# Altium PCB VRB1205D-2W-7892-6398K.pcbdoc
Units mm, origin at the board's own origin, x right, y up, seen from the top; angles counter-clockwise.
Board outline 59.6 x 39.6 mm, 2 copper layers (Top Layer, Bottom Layer); 30 components, 15 nets, 76 pads, 15 vias.
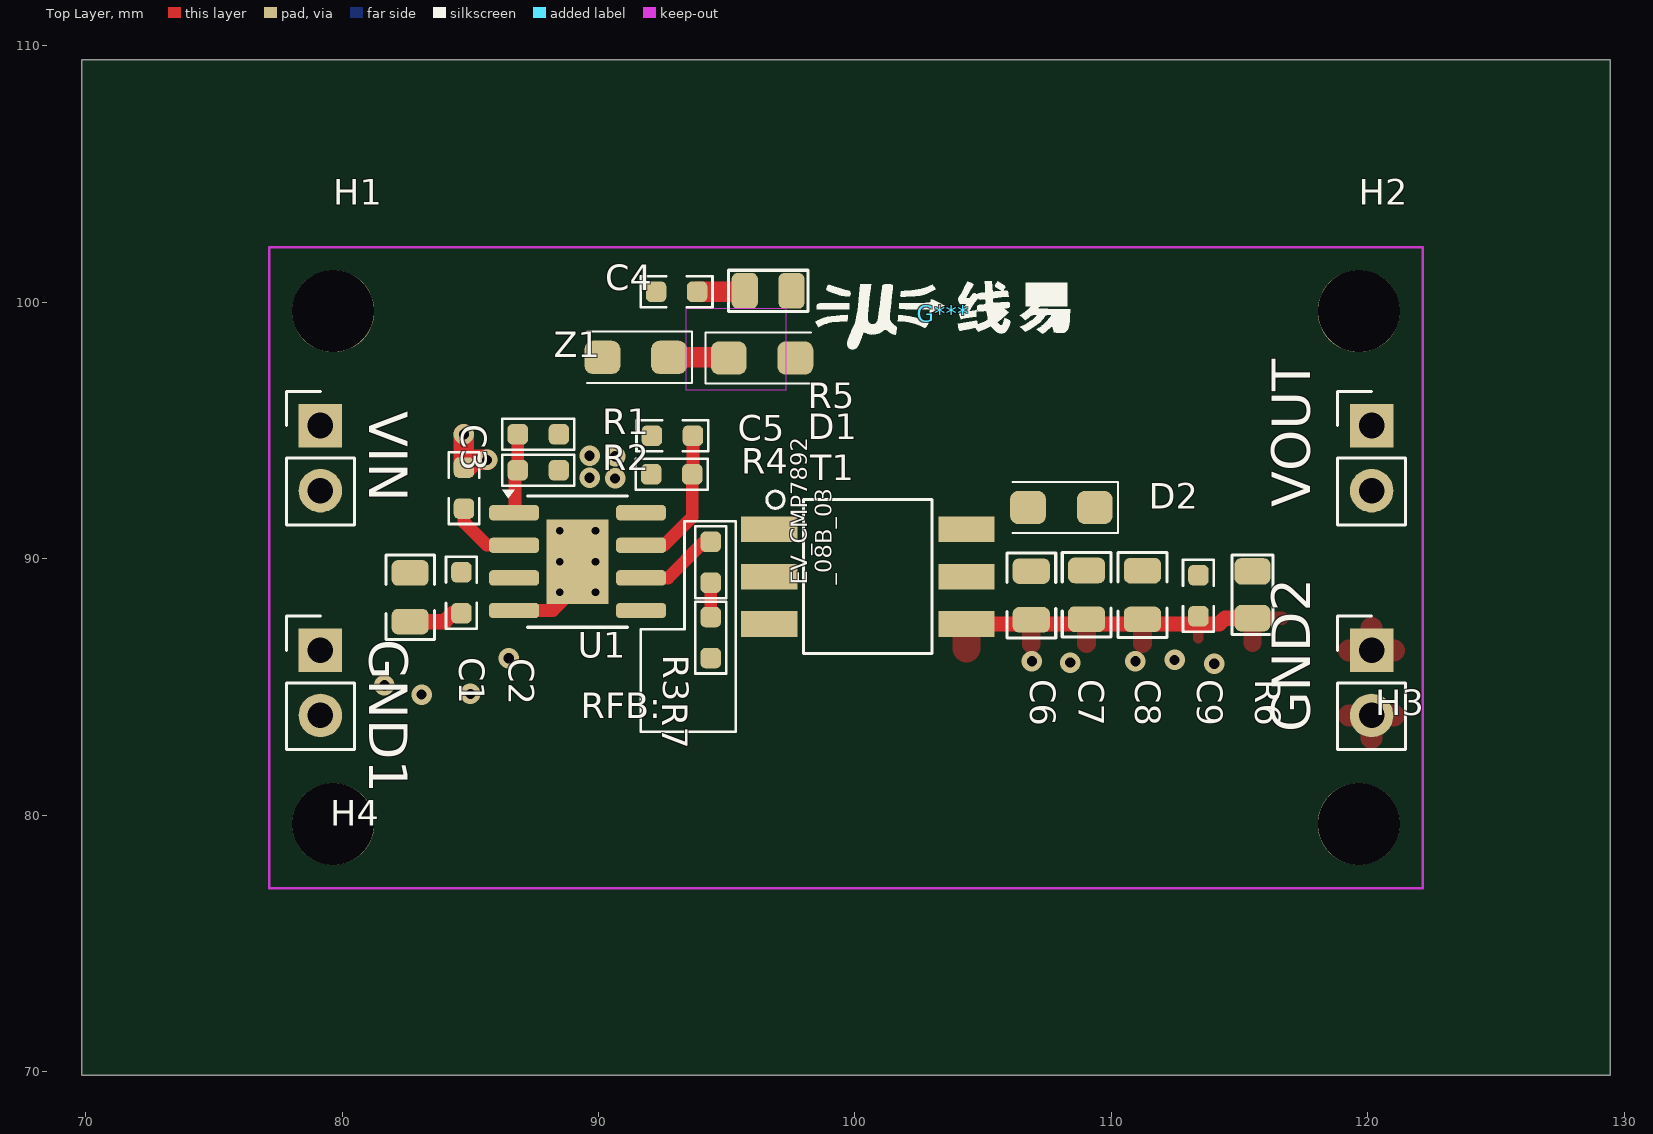
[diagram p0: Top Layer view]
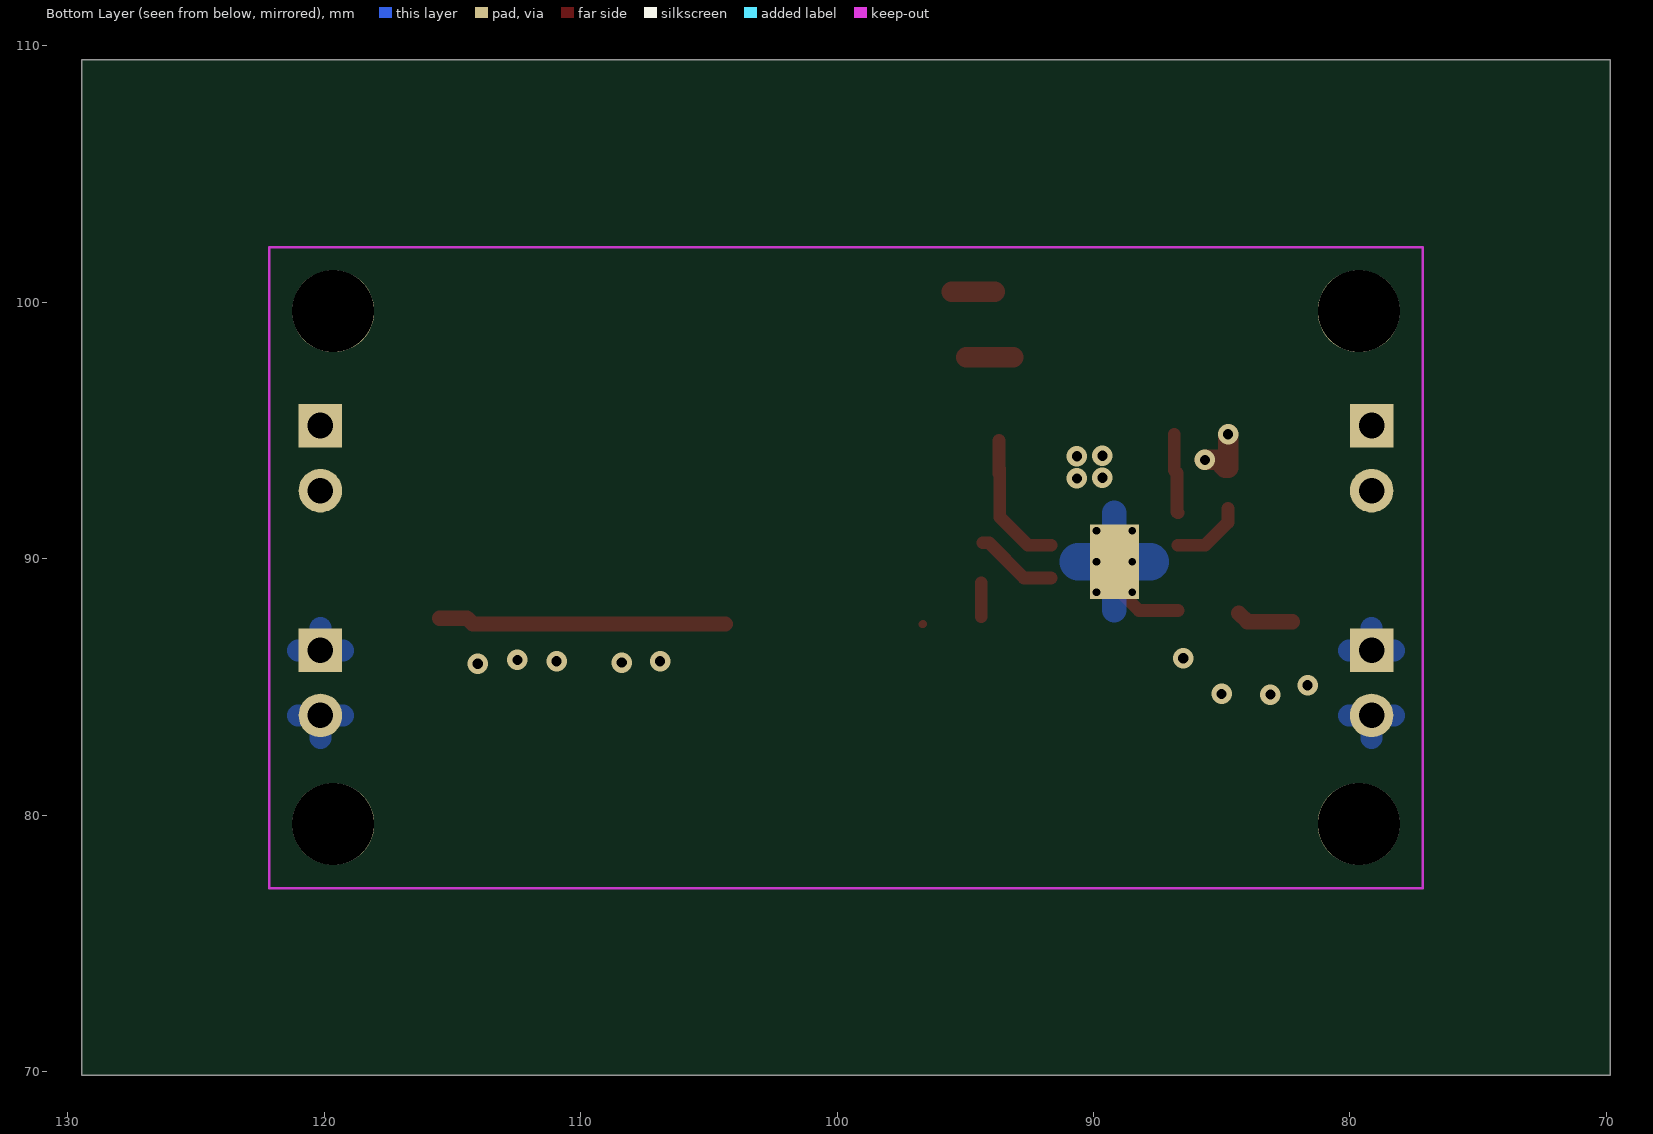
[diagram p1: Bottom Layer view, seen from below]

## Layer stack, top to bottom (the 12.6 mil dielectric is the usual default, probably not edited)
Top Layer: signal copper (thickness not stored)
Dielectric: dielectric 0.32, FR-4, Dk 4.8
Bottom Layer: signal copper (thickness not stored)

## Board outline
129.45,69.85 69.85,69.85 69.85,109.45 129.45,109.45

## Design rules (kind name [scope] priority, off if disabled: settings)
BoardOutlineClearance safeClearance [All] p0: genericclearance=0.254 ignorepadtopadclearanceinfootprint=FALSE except(0: Arc-SplitContinuation Track-SplitContinuation SMDPad-SplitContinuation THPad-SplitContinuation Via-SplitContinuation Fill-SplitContinuation Poly-SplitContinuation Region-SplitContinuation Text-SplitContinuation; 0.201: Track-CutoutEdge SMDPad-CutoutEdge THPad-CutoutEdge Via-CutoutEdge Fill-CutoutEdge Region-CutoutEdge; 0.3: Track-OutlineEdge SMDPad-OutlineEdge THPad-OutlineEdge Via-OutlineEdge Fill-OutlineEdge Region-OutlineEdge Poly-OutlineEdge Text-OutlineEdge)
Clearance safeClearance [(InNet('VIN') OR InNet('/SW') OR InNet('VOUT') OR InNet('GND1') OR InNet('GND2') OR InNet('Net-(D2-A)') OR InNet('NET-(D2-A)') OR InNet('NET-(U1-INTVCC)') OR InNet('NET-(D1-K)') OR InNet('/RFB') OR InNet('/RREF') OR InNet('/EN') OR InNet('NET-(C4-PAD1)') OR InNet('NET-(R3-PAD1)') OR InNet('UNCONNECTED-(T1-PAD5)') OR InNet('UNCONNECTED-(U1-TC-PAD8)'))] p1: gap=0.178 ignorepadtopadclearanceinfootprint=FALSE except(0.201: Track-Track Track-SMDPad SMDPad-SMDPad Track-THPad SMDPad-THPad THPad-THPad Track-Via SMDPad-Via THPad-Via Via-Via Track-Fill SMDPad-Fill THPad-Fill Via-Fill Fill-Fill Track-Region SMDPad-Region THPad-Region Via-Region Fill-Region Region-Region Track-Poly SMDPad-Poly THPad-Poly Via-Poly Fill-Poly Region-Poly Poly-Poly Track-Text SMDPad-Text THPad-Text Via-Text Fill-Text Region-Text Poly-Text Text-Text Track-Hole SMDPad-Hole THPad-Hole Via-Hole Fill-Hole Region-Hole Poly-Hole Text-Hole; 0.3: Track-Sheet SMDPad-Sheet THPad-Sheet Via-Sheet Fill-Sheet Region-Sheet Poly-Sheet Text-Sheet Sheet-Hole)
DiffPairsRouting differentialPair [All] p1: maxuncoupledlength=10 minlimit=6 maxlimit=6 mostfreqgap=6 toplayer_minwidth=5 toplayer_prefwidth=10 toplayer_maxwidth=100 bottomlayer_minwidth=5 bottomlayer_prefwidth=10 bottomlayer_maxwidth=100
PasteMaskExpansion Common [All] p1: expansion=0
PlaneConnect innerPlane [All] p1: planeconnectstyle=Relief reliefexpansion=0.508 reliefentries=4 reliefconductorwidth=0.254 reliefairgap=0.254
PolygonConnect CopperRegion [All] p1: connectstyle=Direct reliefentries=4 reliefconductorwidth=0 polygonreliefangle="90 Angle" airgapwidth=17.7165
PolygonConnect CopperRegion1 [All] p1: connectstyle=Direct reliefentries=4 reliefconductorwidth=0 polygonreliefangle="90 Angle" airgapwidth=17.7165
PolygonConnect CopperRegion2 [All] p1: connectstyle=Direct reliefentries=4 reliefconductorwidth=0 polygonreliefangle="90 Angle" airgapwidth=17.8346
PolygonConnect CopperRegion3 [All] p1: connectstyle=Direct reliefentries=4 reliefconductorwidth=0 polygonreliefangle="90 Angle" airgapwidth=17.8346
PolygonConnect CopperRegion4 [All] p1: connectstyle=Relief reliefentries=4 reliefconductorwidth=0 polygonreliefangle="90 Angle" airgapwidth=17.8346
PolygonConnect CopperRegion5 [All] p1: connectstyle=Direct reliefentries=4 reliefconductorwidth=0 polygonreliefangle="90 Angle" airgapwidth=15.748
PolygonConnect CopperRegion6 [All] p1: connectstyle=Direct reliefentries=4 reliefconductorwidth=0 polygonreliefangle="90 Angle" airgapwidth=17.8346
PolygonConnect CopperRegion7 [All] p1: connectstyle=Relief reliefentries=4 reliefconductorwidth=0 polygonreliefangle="90 Angle" airgapwidth=17.8346
PolygonConnect CopperRegion8 [All] p1: connectstyle=Relief reliefentries=4 reliefconductorwidth=0 polygonreliefangle="90 Angle" airgapwidth=17.8346
RoutingVias viaSize [All] p1: viastyle="Through Hole" holewidth=12.0078 minholewidth=11.811 maxholewidth=236.2204 width=24.0158 minwidth=19.685 maxwidth=393.7008
SolderMaskExpansion Common [All] p1: useseparateexpansions=TRUE expansion=0 expansionbottom=0
Width trackWidth [All] p1: maxlimit=100 minlimit=5 preferedwidth=10

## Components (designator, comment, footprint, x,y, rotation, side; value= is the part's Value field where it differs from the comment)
C1 "10uF/50V" MYLibrary:C0805 82.65,88.493 r270 top
C2 "100nF/50V" MYLibrary:C0603 84.65,88.669 r90 top
C3 "1uF" MYLibrary:C0603 84.75,92.75 r270 top
C4 "470pF" MYLibrary:C0603 93.042,100.408 r180 top
C5 "10pF" MYLibrary:C0603 92.88,94.793 r0 top
C6 "47uF/10V" MYLibrary:C0805 106.875,88.563 r270 top
C7 "47uF/10V" MYLibrary:C0805 109.033,88.589 r270 top
C8 "1uF/10V" MYLibrary:C0805 111.214,88.581 r270 top
C9 "100nF" MYLibrary:C0603 113.394,88.551 r90 top
D1 "PMEG10010" MYLibrary:SOD-323-123-A 96.375,97.825 r0 top
D2 "DSS26/60V/2A" MYLibrary:SOD-323-123-A 108.05,91.993 r180 top
G*** "LOGO" LOGO 103.45,99.55 r0 top
H1 "MountingHole" MountingHole:MountingHole_3.2mm_M3 79.65,99.65 r0 top
H2 "MountingHole" MountingHole:MountingHole_3.2mm_M3 119.65,99.65 r0 top
H3 "MountingHole" MountingHole:MountingHole_3.2mm_M3 119.65,79.65 r0 top
H4 "MountingHole" MountingHole:MountingHole_3.2mm_M3 79.65,79.65 r0 top
R1 "100K" MYLibrary:R0603 87.65,94.85 r180 top
R2 "NC" MYLibrary:R0603 87.65,93.45 r0 top
R3 "132K" MYLibrary:R0603 94.374,89.861 r90 top
R4 "10K" MYLibrary:R0603 92.855,93.288 r180 top
R5 "1K" MYLibrary:R0805 96.613,100.446 r180 top
R6 "220Ω" MYLibrary:R0805 115.503,88.59 r90 top
R7 "10R" MYLibrary:R0603 94.374,86.921 r270 top
T1 "CMB6398K" MYLibrary:EP5_3+3_7.7x5.3 100.5,89.3 r0 top
U1 "~" Package_SO:SOIC-8-1EP_3.9x4.9mm_P1.27mm_EP2.41x3.3mm_ThermalVias 89.181,89.884 r0 top
Z1 "D_Zener_22V" MYLibrary:SOD-323-123-A 91.45,97.85 r180 top
? "Conn_01x02" Connector_PinHeader_2.54mm:PinHeader_1x02_P2.54mm_Vertical 120.15,86.425 r0 top
? "Conn_01x02" Connector_PinHeader_2.54mm:PinHeader_1x02_P2.54mm_Vertical 79.15,86.425 r0 top
? "Conn_01x02" Connector_PinHeader_2.54mm:PinHeader_1x02_P2.54mm_Vertical 120.15,95.19 r0 top
? "Conn_01x02" Connector_PinHeader_2.54mm:PinHeader_1x02_P2.54mm_Vertical 79.15,95.19 r0 top

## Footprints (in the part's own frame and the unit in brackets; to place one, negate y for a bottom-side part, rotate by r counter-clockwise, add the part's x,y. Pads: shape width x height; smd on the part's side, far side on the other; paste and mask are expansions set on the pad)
Connector_PinHeader_2.54mm:PinHeader_1x02_P2.54mm_Vertical [mm]
  rect 1.7x1.7 hole 1: 1(0,0)
  round 1.7 hole 1: 2(0,-2.54)
  silkscreen extent -1.33,-3.87 1.33,1.33
LOGO [mm]
  silkscreen extent -5,-1.4 4.95,1.27
MountingHole:MountingHole_3.2mm_M3 [mm]
  round 3.2 hole 3.2 unplated: ""(0,0)
MYLibrary:C0603 [mm]
  rrect50% 0.8x0.8 smd: 1(-0.8,0) 2(0.8,0)
  silkscreen extent -1.4,-0.6 1.4,0.6
MYLibrary:C0805 [mm]
  rrect50% 1x1.45 smd: 1(-0.95,0) 2(0.95,0)
  silkscreen extent -1.65,-0.95 1.65,0.96
MYLibrary:EP5_3+3_7.7x5.3 [mm]
  rect 2.2x1 smd: 1(-3.85,1.85) 2(-3.85,0) 3(-3.85,-1.85) 4(3.85,-1.85) 5(3.85,0) 6(3.85,1.85)
  silkscreen extent -3.93,-3 2.5,3.33
MYLibrary:R0603 [mm]
  rrect50% 0.8x0.8 smd: 1(-0.8,0) 2(0.8,0)
  silkscreen extent -1.4,-0.6 1.4,0.6
MYLibrary:R0805 [mm]
  rrect48% 1.025x1.4 smd: 1(-0.913,0) 2(0.913,0)
  silkscreen extent -1.55,-0.8 1.55,0.8
MYLibrary:SOD-323-123-A [mm]
  rrect50% 1.4x1.3 smd: 1(-1.3,0) 2(1.3,0)
  silkscreen extent -2.2,-1 1.9,1
Package_SO:SOIC-8-1EP_3.9x4.9mm_P1.27mm_EP2.41x3.3mm_ThermalVias [mm]
  rrect50% 1.95x0.6 smd: 1(-2.475,1.905) 2(-2.475,0.635) 3(-2.475,-0.635) 4(-2.475,-1.905) 5(2.475,-1.905) 6(2.475,-0.635) 7(2.475,0.635) 8(2.475,1.905)
  round 0.5 hole 0.3: 9(-0.7,-1.2) 9(-0.7,0) 9(-0.7,1.2) 9(0.7,-1.2) 9(0.7,0) 9(0.7,1.2)
  rect 1.9x2.9 smd far side: 9(0,0)
  rect 2.41x3.3 smd: 9(0,0)
  rrect49% 1.01x1.38 smd: ""(-0.6,-0.825) ""(-0.6,0.825) ""(0.6,-0.825) ""(0.6,0.825)
  silkscreen extent -2.94,-2.56 1.95,2.79

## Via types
v1: diameter 0.8, hole 0.4, Top Layer to Bottom Layer, 15 vias

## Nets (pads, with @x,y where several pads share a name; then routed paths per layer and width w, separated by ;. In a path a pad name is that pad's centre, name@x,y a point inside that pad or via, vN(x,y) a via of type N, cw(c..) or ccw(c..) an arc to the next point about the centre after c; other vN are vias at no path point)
/EN: R1.2 R2.1 U1.1 | length 3.1
  Top Layer w0.5: U1.1 86.736,91.819 86.736,93.336 R2.1 R1.2
/RFB: R3.2 U1.6 | length 3.2
  Top Layer w0.5: U1.6 92.702,89.249 94.074,90.621 R3.2@94.304,90.621
/RREF: C5.2 R4.1 U1.7 | length 5.7
  Top Layer w0.5: U1.7 92.552,90.519 93.656,91.623 R4.1@93.656,93.499 ; R4.1 93.68,93.313 C5.2@93.68,94.609
/SW: D1.2 R5.1 R7.2 T1.2 T1.3 U1.5 | length 0
  Top Layer w0.3: T1.3 T1.3@96.665,87.435
GND1: ?.1@79.15,86.425 ?.2@79.15,83.885 C1.2 C2.1 C3.1 C5.1 R2.2 R4.2 U1. U1.4 U1.9 | length 8.4
  Top Layer w0.25: U1.9@89.181,88.94 U1.9@89.181,89.884
  Top Layer w0.5: U1.4 88.22,87.979 U1.9@89.181,88.94
  Top Layer w0.6: C1.2@82.233,87.543 83.999,87.543 C2.1@84.326,87.869
  Top Layer w0.8: v1(84.75,94.85) C3.1 84.85,93.55 85.15,93.85 v1(85.65,93.85)
  other v1: 83.097,84.697 85.002,84.722 81.646,85.059 86.501,86.119 89.65,93.15 90.641,93.13 89.65,94.014 90.641,93.993
GND2: ?.1@120.15,86.425 ?.2@120.15,83.885 C6.2 C7.2 C8.2 C9.1 R6.1 T1.4 | length 11.2
  Top Layer w0.6: T1.4 114.203,87.45 114.431,87.678 R6.1
  other v1: 114.013,85.896 108.399,85.947 106.901,85.998 110.939,85.998 112.463,86.049
NET-(C4-PAD1): C4.1 R5.2 | length 1.7
  Top Layer w0.8: C4.1 R5.2@95.53,100.408
NET-(D1-K): D1.1 Z1.1 | length 1.8
  Top Layer w0.8: Z1.1@93.127,97.85 D1.1@94.95,97.85
NET-(D2-A): D2.2 T1.6
NET-(R3-PAD1): R3.1 R7.1 | length 1.3
  Top Layer w0.25: R7.1@94.374,87.741 R7.1@94.394,87.721
  Top Layer w0.5: R7.1@94.374,87.741 R3.1
NET-(U1-INTVCC): C3.2 U1.2 | length 2.9
  Top Layer w0.5: C3.2 84.75,91.415 85.646,90.519 U1.2
UNCONNECTED-(T1-PAD5): T1.5
UNCONNECTED-(U1-TC-PAD8): U1.8
VIN: ?.1@79.15,95.19 ?.2@79.15,92.65 C1.1 C2.2 C4.2 R1.1 T1.1 U1.3 Z1.2
VOUT: ?.1@120.15,95.19 ?.2@120.15,92.65 C6.1 C7.1 C8.1 C9.2 D2.1 R6.2
pads on no net: H1. H2. H3. H4.

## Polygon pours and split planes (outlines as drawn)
GND1 on Bottom Layer (solid, remove dead copper, pour order 14): 77.146,102.197 77.103,77.149 99.1,77.188 99.057,102.217
GND2 on Top Layer (solid, remove dead copper, pour order 0): 122.187,88.109 122.209,77.208 103.225,77.208 103.269,88.157
NET-(D2-A) on Top Layer (solid, remove dead copper, pour order 2): 103.319,93.237 103.319,90.646 107.104,90.646 107.104,93.237
/SW on Top Layer (solid, remove dead copper, pour order 4): 90.683,88.279 90.683,85.343 99.08,85.368 99.051,101.051 97.376,101.051 97.376,92.119 97.909,92.119 97.909,89.656 95.217,89.605 95.217,88.284
GND2 on Bottom Layer (solid, remove dead copper, pour order 16): 103.373,102.173 122.215,102.173 122.193,77.033 103.179,77.033
GND1 on Top Layer (solid, remove dead copper, pour order 6): 87.976,94.649 92.676,94.649 92.676,92.649 90.676,92.649 90.476,92.449 90.476,91.624 90.286,91.434 90.286,90.474 90.286,87.393 88.133,87.393 88.076,90.474 88.076,91.399 87.976,91.499
VOUT on Top Layer (solid, remove dead copper, pour order 8): 122.287,88.803 122.287,102.223 103.37,102.223 103.37,94.38 103.37,88.755
VIN on Top Layer (solid, remove dead copper, pour order 10): 99.078,88.919 99.057,102.216 77.174,102.197 77.153,88.919
GND1 on Top Layer (solid, remove dead copper, pour order 12): 77.188,88.767 99.103,88.767 99.103,77.107 77.143,77.068

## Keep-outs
Top Layer:
  region: 93.406,96.595 97.325,96.595 97.325,99.747 93.406,99.747
Board Outline Layer:
  lines w0.1: 77.15,77.15 122.15,77.15 122.15,102.15 77.15,102.15 77.15,77.15

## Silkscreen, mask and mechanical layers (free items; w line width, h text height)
Top Silkscreen Layer:
  lines w0.1: 91.65,83.25 91.65,86.95 91.65,87.25 93.35,87.25 93.35,91.45 95.35,91.45 95.35,83.25 91.65,83.25
  text "VIN" at 81.05,95.75 h1.5 r270
  text "VOUT" at 117.754,92.011 h1.5 r90
  text "EV_CMP7892 / _08B_03" at 99.085,88.977 h0.64 r90
  text "GND1" at 81.05,86.85 h1.5 r270
  text "RFB:" at 89.306,83.77 h1
  text "GND2" at 117.754,83.238 h1.5 r90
